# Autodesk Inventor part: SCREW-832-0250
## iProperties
Created: 2007-08
Part Number: SCREW-832-0250
Material: Stainless Steel
Document SubType Name: Modeling
Density: 8.08 g/cm^3
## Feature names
1. Base1
